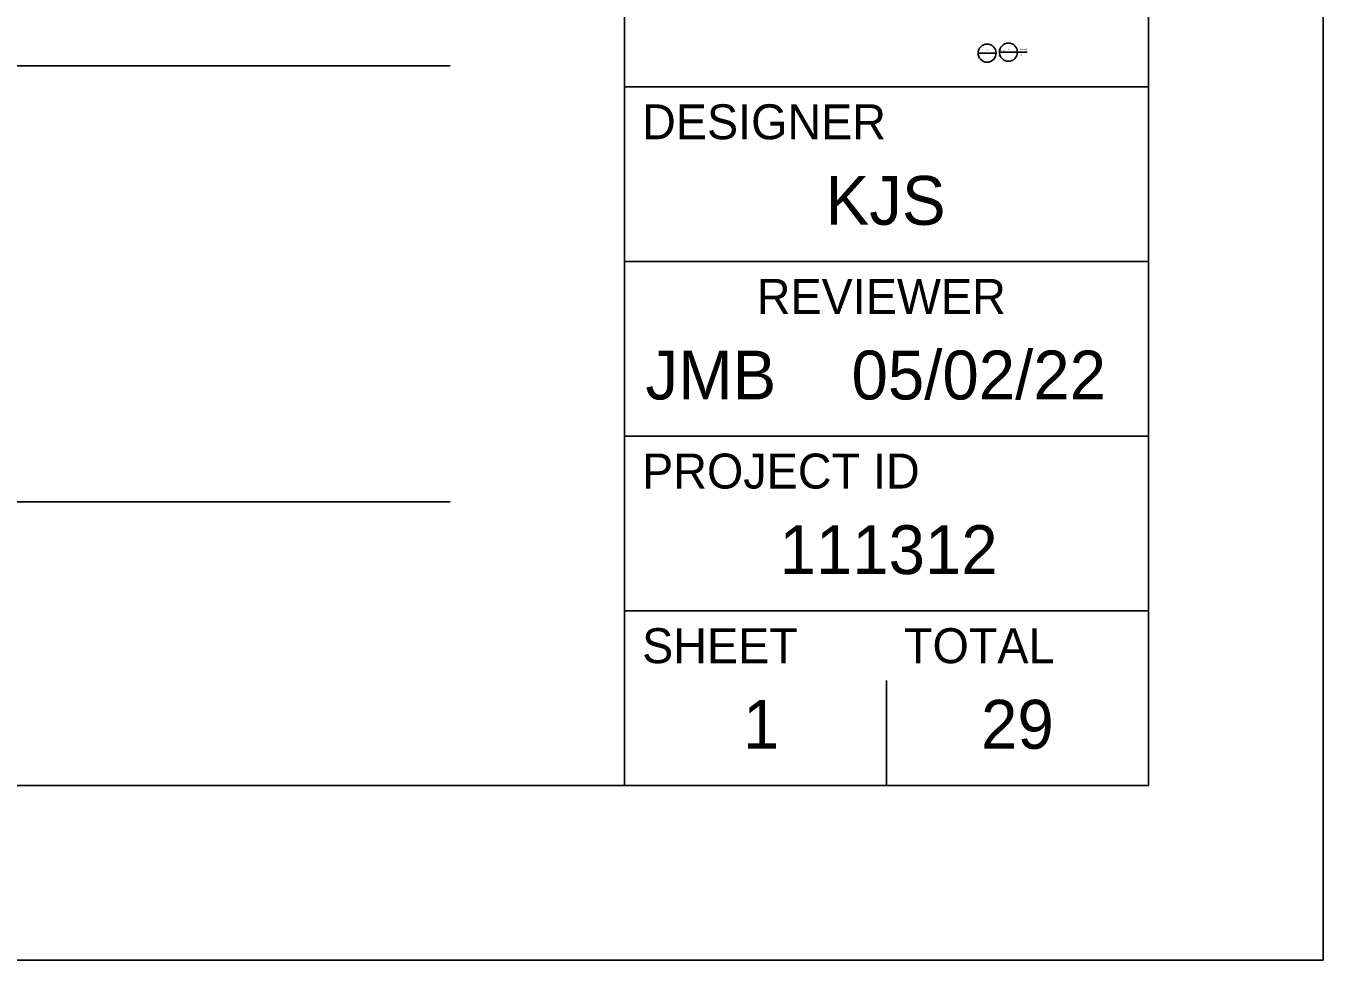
# Model space of a CAD drawing. Extents: x 0 to 84, y -106 to 22.
# Drawn here: x 30.285 to 34, y 0 to 2.674 of the extents above; entities that cross this region are included whole.
import ezdxf

# ---------------------------------------------------------------- set-up
doc = ezdxf.new("R2010")
doc.units = 0
for name, color, linetype in [('CS-ALGN-CNTR', 7, 'Continuous'), ('CS-ALGN-TEXT', 7, 'Continuous'), ('CS-ANNO', 7, 'Continuous'), ('CS-ANNO-MATC-MASK', 7, 'Continuous')]:
    doc.layers.add(name, color=color, linetype=linetype)

msp = doc.modelspace()

# ---------------------------------------------------------------- linework, layer by layer
at = {"layer": 'CS-ALGN-CNTR'}
msp.add_lwpolyline([(0, 0), (34, 0), (34, 22), (0, 22)], close=True, dxfattribs=at)
at = {"layer": 'CS-ALGN-TEXT'}
for p, q in [((32, 0.5), (32, 21.5)), ((32, 2.5), (33.5, 2.5)), ((32, 2), (33.5, 2)), ((32, 1.5), (33.5, 1.5)), ((32, 1), (33.5, 1))]:
    msp.add_line(p, q, dxfattribs=at)
msp.add_lwpolyline([(1.5, 21.5), (33.5, 21.5), (33.5, 0.5), (1.5, 0.5)], close=True, dxfattribs=at)
at = {"layer": 'CS-ANNO'}
for p, q in [((26.6348, 2.5598), (31.5, 2.5598)), ((26.6348, 1.3116), (31.5, 1.3116)), ((32.75, 0.5), (32.75, 0.8)), ((32.375, 0.675), (32.375, 0.675))]:
    msp.add_line(p, q, dxfattribs=at)
at = {"layer": 'CS-ANNO-MATC-MASK'}
for p, q in [((33.0119, 2.5966), (33.0639, 2.5966)), ((33.073, 2.5994), (33.125, 2.5994)), ((33.0992, 2.5994), (33.1529, 2.5994))]:
    msp.add_line(p, q, dxfattribs=at)
for centre in [(33.0379, 2.5966), (33.099, 2.5994)]:
    msp.add_circle(centre, 0.026, dxfattribs=at)

# ---------------------------------------------------------------- texts
at = {"layer": 'CS-ANNO'}
for s, height, p in [('DESIGNER', 0.1, (32.05, 2.35)), ('KJS', 0.14, (32.5757, 2.105)), ('REVIEWER', 0.1, (32.3783, 1.85)), ('05/02/22', 0.14, (32.6497, 1.605)), ('JMB', 0.14, (32.0596, 1.605)), ('PROJECT ID', 0.1, (32.05, 1.35)), ('111312', 0.14, (32.4435, 1.105)), ('SHEET', 0.1, (32.05, 0.85)), ('TOTAL', 0.1, (32.8, 0.85)), ('1', 0.14, (32.3386, 0.605)), ('29', 0.14, (33.0206, 0.605))]:
    msp.add_text(s, height=height, dxfattribs=at).set_placement(p)
at = {"layer": 'CS-ANNO-MATC-MASK'}
for s, p in [('4', (33.0367, 2.6032)), ('Drawing-1', (33.0705, 2.6032)), ('6', (33.0978, 2.6059)), ('Drawing-2', (33.1318, 2.6059)), ('1:2', (33.0705, 2.5868)), ('1:2', (33.1318, 2.5895))]:
    msp.add_text(s, height=0.00328, dxfattribs=at).set_placement(p)

doc.saveas('drawing.dxf')
